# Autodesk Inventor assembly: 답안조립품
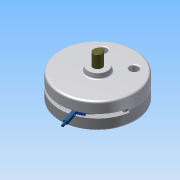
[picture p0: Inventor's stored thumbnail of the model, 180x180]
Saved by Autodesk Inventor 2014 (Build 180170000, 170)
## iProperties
Created: 2015-06
Part Number: 답안조립품
Document SubType Name: Assembly
Designer: Administrator
Author: Administrator
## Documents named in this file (10)
- C:\Documents and Settings\Administrator\바탕 화면\450631V1027\답안조립품.iam
- C:\Documents and Settings\Administrator\바탕 화면\450631V1027\1-본체.ipt
- C:\Documents and Settings\Administrator\바탕 화면\450631V1027\베어링62_22.ipt
- C:\Documents and Settings\Administrator\바탕 화면\450631V1027\덮개.ipt
- C:\Documents and Settings\Administrator\바탕 화면\450631V1027\축.ipt
- C:\Documents and Settings\Administrator\바탕 화면\450631V1027\멈춤링.ipt
- C:\Documents and Settings\Administrator\바탕 화면\450631V1027\슬라이더2.ipt
- C:\Documents and Settings\Administrator\바탕 화면\450631V1027\슬라이더.ipt
- C:\Documents and Settings\Administrator\바탕 화면\450631V1027\평행핀.ipt
- C:\Documents and Settings\Administrator\바탕 화면\450631V1027\M10x35.ipt
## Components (8 placed, 5 different names)
1. 1-본체:1
2. KS B 2023 62/22 - 22 x 50 x 14:1
3. KS B 2023 62/22 - 22 x 50 x 14:2
4. KS B 1336 22 x 1.2:1
5. KS B 1336 22 x 1.2:2
6. KS B 1320 B B 5 x  20:1
7. KS B 1003 - 미터 M 10 x 35:1
8. KS B 1003 - 미터 M 10 x 35:2
